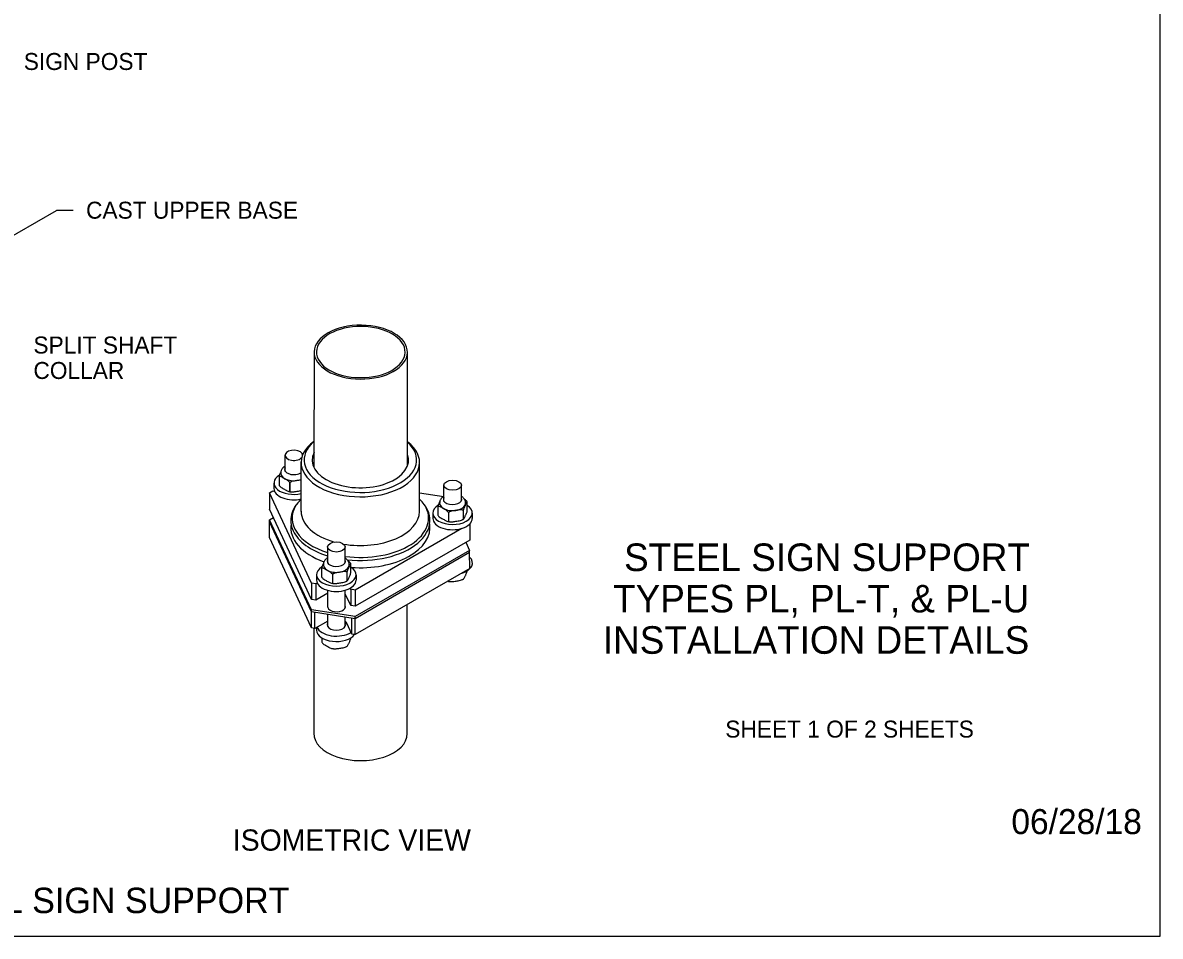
# Model space of a CAD drawing. Extents: x 99862 to 103151, y 100000 to 105076.
# Drawn here: x 102079 to 103151, y 100000 to 100861 of the extents above; entities that cross this region are included whole.
import ezdxf

# ---------------------------------------------------------------- set-up
doc = ezdxf.new("R2010")
doc.units = 0
for name, color, linetype in [('Level 1', 7, 'Continuous'), ('Level 12', 7, 'Continuous'), ('Level 15', 7, 'Continuous'), ('Level 20', 7, 'Continuous'), ('Level 4', 7, 'Continuous'), ('Level 5', 7, 'Continuous'), ('Level 6', 7, 'Continuous'), ('Level 62', 7, 'Continuous'), ('Level 63', 7, 'Continuous'), ('Level 7', 7, 'Continuous')]:
    doc.layers.add(name, color=color, linetype=linetype)

msp = doc.modelspace()

# ---------------------------------------------------------------- linework, layer by layer
at = {"layer": 'Level 1'}
msp.add_lwpolyline([(99862, 99999.5), (103151, 99999.5), (103151, 102075.5), (99862, 102075.5)], close=True, dxfattribs=at)
at = {"layer": 'Level 12'}
for p, q in [((102326.2, 100437.8), (102326.2, 100452.9)), ((102342.8, 100452.9), (102342.8, 100452.9)), ((102320.6, 100433.1), (102320.6, 100424.6)), ((102315.8, 100426.8), (102315.8, 100421.7)), ((102330.7, 100427.2), (102330.7, 100418.8)), ((102330.7, 100418.8), (102330.7, 100427.2)), ((102476, 100409.5), (102476, 100424.7)), ((102492.5, 100409.9), (102492.5, 100424.7)), ((102329.9, 100418.8), (102329.9, 100418.8)), ((102331.8, 100418.5), (102331.8, 100418.5)), ((102470.3, 100404.8), (102470.3, 100396.4)), ((102494.2, 100401.1), (102494.2, 100392.7)), ((102497.9, 100400.7), (102497.9, 100409.1)), ((102465.6, 100398.5), (102465.6, 100393.5)), ((102480.4, 100399), (102480.4, 100390.6)), ((102502.7, 100398.5), (102502.7, 100393.5)), ((102366.4, 100351.3), (102366.4, 100366.5)), ((102382.9, 100351.7), (102382.9, 100366.5)), ((102388.3, 100342.4), (102388.3, 100350.9)), ((102355.9, 100340.3), (102355.9, 100335.3)), ((102360.7, 100346.6), (102360.7, 100338.2)), ((102370.8, 100340.8), (102370.8, 100332.3)), ((102384.6, 100342.9), (102384.6, 100334.5)), ((102393.1, 100340.3), (102393.1, 100335.3)), ((102494.5, 100336.4), (102494.5, 100336.4)), ((102366.4, 100309.9), (102366.4, 100325.6)), ((102382.9, 100309.3), (102382.9, 100325.7)), ((102479.8, 100334.2), (102479.8, 100334.2)), ((102481.7, 100333.9), (102481.7, 100333.9)), ((102493.9, 100336), (102493.8, 100336)), ((102366.4, 100291.5), (102366.4, 100302.9)), ((102382.9, 100291.5), (102382.9, 100300.4)), ((102356, 100290.7), (102356, 100288.1)), ((102360.8, 100280.9), (102360.8, 100276.7)), ((102384.2, 100272.7), (102384.2, 100272.7)), ((102384.8, 100273.1), (102384.8, 100273.1)), ((102370.1, 100270.9), (102370.1, 100270.9)), ((102372.1, 100270.6), (102372.1, 100270.6))]:
    msp.add_line(p, q, dxfattribs=at)
for centre, major_axis, ratio, start_param, end_param in [((102334.5, 100452.9), (-8.26, 0), 0.57735, 3.126776, 9.061237), ((102334.4, 100426.8), (-18.6, 0), 0.57735, 5.527185, 8.246196), ((102334.4, 100436), (-12.2, 0), 0.57735, 0, 2.190456), ((102334.4, 100439.5), (8.72, 0), 0.546299, 2.771788, 5.664646), ((102334.4, 100421.7), (-18.6, 0), 0.57735, 0, 1.962888), ((102484.1, 100411.3), (8.72, 0), 0.546299, 2.771788, 6.566843), ((102484.1, 100398.5), (-18.6, 0), 0.57735, 5.527185, 10.157185), ((102484.1, 100407.8), (-12.2, 0), 0.57735, 0, 3.141593), ((102484.1, 100393.5), (-18.6, 0), 0.57735, 0, 3.141593), ((102374.5, 100340.3), (-18.6, 0), 0.57735, 5.527185, 10.157185), ((102374.5, 100349.6), (-12.2, 0), 0.57735, 0, 3.141593), ((102374.5, 100353), (8.72, 0), 0.546299, 2.771788, 6.566843), ((102484.2, 100351.4), (18.6, 0), 0.57735, 5.200622, 6.819314), ((102374.5, 100335.3), (-18.6, 0), 0.57735, 0, 3.141593), ((102374.6, 100293.2), (-8.77, 0), 0.57735, 5.938484, 9.769479), ((102374.6, 100288.1), (18.6, 0), 0.57735, 3.141593, 5.883676), ((102374.6, 100293.2), (-18.6, 0), 0.57735, 0.209677, 2.408341)]:
    msp.add_ellipse(centre, major_axis=major_axis, ratio=ratio, start_param=start_param, end_param=end_param, dxfattribs=at)
for centre in [(102484.2, 100424.7), (102374.6, 100366.5)]:
    msp.add_ellipse(centre, major_axis=(-8.26, 0), ratio=0.57735, dxfattribs=at)
for points, degree in [([(102322.4, 100437.8), (102321.9, 100436.7), (102321.3, 100435.5), (102320.7, 100433.7), (102320.6, 100433.4), (102320.6, 100433.1)], 3), ([(102330.7, 100427.2), (102330.5, 100427.5), (102330.2, 100427.8), (102328.7, 100429.3), (102327, 100430.2), (102325.6, 100431), (102324.2, 100431.8), (102322.6, 100432.8), (102321, 100433.1), (102320.8, 100433.1), (102320.6, 100433.1)], 3), ([(102326.2, 100442.7), (102325.2, 100442.1), (102324.2, 100441.2), (102323.1, 100439.6), (102322.7, 100438.8), (102322.3, 100437.5), (102322.1, 100436.7), (102322.1, 100436)], 3), ([(102320.6, 100424.6), (102320.8, 100424.3), (102321, 100424.1), (102322.6, 100422.6), (102324.2, 100421.7), (102325.6, 100420.9), (102327, 100420.1), (102328.6, 100419.1), (102329.9, 100418.8)], 3), ([(102341.3, 100429.6), (102340, 100429.5), (102338.7, 100429.3), (102337.6, 100429.1), (102335.7, 100428.8), (102333.4, 100428.6), (102331.3, 100427.6), (102331, 100427.4), (102330.7, 100427.2)], 3), ([(102329.9, 100418.8), (102330.5, 100418.7), (102331.2, 100418.6), (102331.8, 100418.5)], 2), ([(102331.8, 100418.5), (102333.6, 100418.3), (102335.8, 100418.7), (102337.6, 100419), (102338.8, 100419.2), (102340.2, 100419.4), (102341.5, 100419.7)], 3), ([(102476, 100414.5), (102475, 100413.8), (102474, 100412.9), (102472.8, 100411.4), (102472.4, 100410.6), (102472, 100409.3), (102471.9, 100408.5), (102471.9, 100407.8)], 3), ([(102496.4, 100407.8), (102496.4, 100409.1), (102495.9, 100410.6), (102494.6, 100412.7), (102493.5, 100413.6), (102492.5, 100414.3)], 3), ([(102497.9, 100409.1), (102497.7, 100409.4), (102497.5, 100409.7), (102496.7, 100410.5), (102496, 100410.9), (102495.4, 100411.4)], 3), ([(102472.1, 100409.6), (102471.6, 100408.5), (102471, 100407.3), (102470.5, 100405.5), (102470.4, 100405.2), (102470.3, 100404.8)], 3), ([(102480.4, 100399), (102480.2, 100399.3), (102479.9, 100399.6), (102478.4, 100401.1), (102476.8, 100402), (102475.4, 100402.8), (102474, 100403.6), (102472.3, 100404.6), (102470.8, 100404.9), (102470.5, 100404.9), (102470.3, 100404.8)], 3), ([(102494.2, 100401.1), (102493.9, 100401.3), (102493.6, 100401.3), (102491.5, 100401.6), (102489.2, 100401.2), (102487.3, 100400.9), (102485.4, 100400.6), (102483.2, 100400.3), (102481.1, 100399.4), (102480.7, 100399.2), (102480.4, 100399)], 3), ([(102497.9, 100409.1), (102497.9, 100409.1), (102497.8, 100409), (102497.2, 100408.4), (102496.6, 100407.1), (102496.1, 100406), (102495.6, 100404.9), (102495, 100403.6), (102494.4, 100401.8), (102494.3, 100401.5), (102494.2, 100401.1)], 3), ([(102494.3, 100392.8), (102494.4, 100392.8), (102494.5, 100392.8), (102495, 100393.4), (102495.6, 100394.8), (102496.1, 100395.9), (102496.6, 100396.9), (102497.2, 100398.2), (102497.8, 100400), (102497.9, 100400.3), (102497.9, 100400.7)], 3), ([(102470.3, 100396.4), (102470.5, 100396.1), (102470.8, 100395.8), (102472.3, 100394.3), (102474, 100393.5), (102475.4, 100392.7), (102476.7, 100391.9), (102478.3, 100390.9), (102479.6, 100390.6)], 3), ([(102479.6, 100390.6), (102480.3, 100390.5), (102480.9, 100390.4), (102481.6, 100390.3)], 2), ([(102481.6, 100390.3), (102483.3, 100390.1), (102485.5, 100390.5), (102487.3, 100390.8), (102489.2, 100391.1), (102491.5, 100391.4), (102493.4, 100392.2), (102493.6, 100392.3), (102493.7, 100392.4)], 3), ([(102493.7, 100392.4), (102493.9, 100392.5), (102494.1, 100392.6), (102494.3, 100392.7), (102494.3, 100392.7), (102494.3, 100392.8)], 3), ([(102362.5, 100351.3), (102362, 100350.3), (102361.4, 100349.1), (102360.9, 100347.3), (102360.8, 100346.9), (102360.7, 100346.6)], 3), ([(102366.4, 100356.3), (102365.3, 100355.6), (102364.3, 100354.7), (102363.2, 100353.2), (102362.8, 100352.4), (102362.4, 100351), (102362.3, 100350.2), (102362.3, 100349.6)], 3), ([(102386.7, 100349.6), (102386.7, 100350.9), (102386.3, 100352.4), (102384.9, 100354.4), (102383.9, 100355.4), (102382.9, 100356.1)], 3), ([(102388.3, 100350.9), (102388.2, 100350.9), (102388.1, 100350.8), (102387.6, 100350.2), (102387, 100348.8), (102386.5, 100347.7), (102386, 100346.6), (102385.3, 100345.4), (102384.8, 100343.6), (102384.7, 100343.2), (102384.6, 100342.9)], 3), ([(102388.3, 100350.9), (102388.1, 100351.2), (102387.8, 100351.4), (102387, 100352.2), (102386.4, 100352.7), (102385.8, 100353.1)], 3), ([(102370.8, 100340.8), (102370.6, 100341.1), (102370.3, 100341.3), (102368.8, 100342.8), (102367.1, 100343.7), (102365.7, 100344.5), (102364.4, 100345.3), (102362.7, 100346.3), (102361.2, 100346.6), (102360.9, 100346.6), (102360.7, 100346.6)], 3), ([(102360.7, 100338.2), (102360.9, 100337.9), (102361.2, 100337.6), (102362.7, 100336.1), (102364.4, 100335.2), (102365.7, 100334.4), (102367.1, 100333.6), (102368.7, 100332.6), (102370, 100332.4)], 3), ([(102384.6, 100342.9), (102384.3, 100343), (102384, 100343.1), (102381.9, 100343.4), (102379.6, 100343), (102377.7, 100342.7), (102375.8, 100342.4), (102373.6, 100342.1), (102371.5, 100341.2), (102371.1, 100341), (102370.8, 100340.8)], 3), ([(102384.7, 100334.5), (102384.8, 100334.5), (102384.8, 100334.6), (102385.3, 100335.2), (102386, 100336.5), (102386.5, 100337.6), (102387, 100338.7), (102387.6, 100339.9), (102388.1, 100341.8), (102388.2, 100342.1), (102388.3, 100342.4)], 3), ([(102493.8, 100336), (102494, 100336.1), (102494.2, 100336.2), (102494.4, 100336.3), (102494.4, 100336.3), (102494.5, 100336.4)], 3), ([(102494.5, 100336.4), (102494.5, 100336.4), (102494.6, 100336.4), (102495.1, 100337), (102495.7, 100338.4), (102496.2, 100339.5), (102496.7, 100340.6), (102497.3, 100341.8), (102497.9, 100343.6), (102498, 100343.9), (102498, 100344.2)], 3), ([(102370, 100332.4), (102370.7, 100332.3), (102371.3, 100332.2), (102371.9, 100332.1)], 2), ([(102371.9, 100332.1), (102373.7, 100331.9), (102375.9, 100332.3), (102377.7, 100332.6), (102379.6, 100332.9), (102381.9, 100333.1), (102383.8, 100334), (102383.9, 100334.1), (102384.1, 100334.2)], 3), ([(102384.1, 100334.2), (102384.3, 100334.3), (102384.5, 100334.4), (102384.7, 100334.5), (102384.7, 100334.5), (102384.7, 100334.5)], 3), ([(102479.8, 100334.2), (102480.4, 100334.1), (102481.1, 100334), (102481.7, 100333.9)], 2), ([(102481.7, 100333.9), (102483.4, 100333.7), (102485.6, 100334.1), (102487.5, 100334.4), (102489.3, 100334.7), (102491.6, 100335), (102493.5, 100335.8), (102493.7, 100335.9), (102493.9, 100336)], 3), ([(102360.8, 100276.7), (102361, 100276.4), (102361.3, 100276.1), (102362.8, 100274.6), (102364.5, 100273.8), (102365.9, 100273), (102367.2, 100272.2), (102368.9, 100271.2), (102370.1, 100270.9)], 3), ([(102372.1, 100270.6), (102373.8, 100270.4), (102376, 100270.8), (102377.8, 100271.1), (102379.7, 100271.4), (102382, 100271.7), (102383.9, 100272.5), (102384.1, 100272.6), (102384.2, 100272.7)], 3), ([(102384.2, 100272.7), (102384.4, 100272.8), (102384.6, 100272.9), (102384.8, 100273), (102384.8, 100273), (102384.8, 100273.1)], 3), ([(102384.8, 100273.1), (102384.9, 100273.1), (102384.9, 100273.1), (102385.5, 100273.7), (102386.1, 100275.1), (102386.6, 100276.2), (102387.1, 100277.3), (102387.7, 100278.5), (102388.3, 100280.3), (102388.3, 100280.6), (102388.4, 100280.9)], 3), ([(102370.1, 100270.9), (102370.8, 100270.8), (102371.4, 100270.7), (102372.1, 100270.6)], 2)]:
    msp.add_open_spline(points, degree=degree, dxfattribs=at)
at = {"layer": 'Level 15'}
for p in [(102054.4, 100651.3), (102126.7, 100683.8)]:
    msp.add_line(p, (102110.7, 100683.8), dxfattribs=at)
at = {"layer": 'Level 4'}
for p, q in [((102341.5, 100400.1), (102341.5, 100446.9)), ((102453, 100400.1), (102453, 100446.5))]:
    msp.add_line(p, q, dxfattribs=at)
for centre, major_axis, start_param, end_param in [((102397.2, 100446), (-55.8, 0), 5.613202, 10.075608), ((102397.2, 100448.5), (-53, 0), 5.682747, 10.002966), ((102397.2, 100448.5), (-45.4, 0), 6.008223, 9.64062), ((102397.2, 100391.6), (-65.6, 0), 5.728235, 7.364166), ((102397.2, 100391.6), (-65.6, 0), 1.379992, 3.696446), ((102397.2, 100393.8), (-64.3, 0), 5.953629, 7.353253), ((102397.2, 100393.8), (-64.3, 0), 1.345662, 3.471149), ((102397.2, 100400.1), (-55.8, 0), 6.282944, 7.402051), ((102397.2, 100400.1), (-55.8, 0), 1.282094, 3.141666), ((102397.2, 100384.8), (-65.6, 0), 6.192734, 7.303736), ((102397.2, 100384.8), (-65.6, 0), 1.439835, 3.232044)]:
    msp.add_ellipse(centre, major_axis=major_axis, ratio=0.57735, start_param=start_param, end_param=end_param, dxfattribs=at)
at = {"layer": 'Level 5'}
for p, q in [((102353.6, 100550.6), (102353.5, 100441.4)), ((102441.6, 100442.9), (102441.6, 100550.3)), ((102441.4, 100190.4), (102441.3, 100312.1)), ((102353.4, 100289.9), (102353.3, 100190.1))]:
    msp.add_line(p, q, dxfattribs=at)
for centre, major_axis, end_param in [((102397.6, 100550.2), (-44, 0), 12.552004), ((102397.6, 100550.3), (-41.8, 0), 12.552004), ((102397.4, 100190.5), (-44, 0), 9.426883)]:
    msp.add_ellipse(centre, major_axis=major_axis, ratio=0.57735, start_param=6.268969, end_param=end_param, dxfattribs=at)
at = {"layer": 'Level 6'}
for p, q in [((102311.5, 100417.5), (102314.6, 100419.3)), ((102311.5, 100417.5), (102311.5, 100402.2)), ((102351.1, 100332.3), (102311.5, 100417.5)), ((102314.6, 100419.3), (102316.4, 100418.9)), ((102453, 100417.7), (102476, 100414.1)), ((102351.1, 100317), (102311.5, 100402.2)), ((102311.6, 100375.4), (102311.7, 100390.3)), ((102492.8, 100384), (102392.2, 100325.9)), ((102500.3, 100388.2), (102500.3, 100373)), ((102351.2, 100290.2), (102311.6, 100375.4)), ((102500.3, 100373), (102392.2, 100310.6)), ((102500.4, 100346.2), (102500.1, 100361.2)), ((102500.4, 100346.2), (102392.3, 100283.9)), ((102355.2, 100331.7), (102351.1, 100332.3)), ((102351.1, 100332.3), (102351.1, 100317)), ((102356.6, 100332.4), (102355.2, 100331.7)), ((102355.2, 100331.7), (102355.2, 100316.4)), ((102388.1, 100326.6), (102387.6, 100327.6)), ((102392.2, 100325.9), (102388.1, 100326.6)), ((102388.1, 100326.6), (102388.1, 100311.3)), ((102392.2, 100325.9), (102392.2, 100310.6)), ((102355.2, 100316.4), (102351.1, 100317)), ((102366.4, 100322.8), (102355.2, 100316.4)), ((102388.1, 100311.3), (102383.5, 100321.1)), ((102351.2, 100290.2), (102351.2, 100305.3)), ((102354.4, 100289.7), (102354.4, 100304.8)), ((102392.2, 100310.6), (102388.1, 100311.3)), ((102366.4, 100296.7), (102354.4, 100289.7)), ((102389.2, 100284.3), (102384.3, 100294.8)), ((102389.2, 100284.3), (102389.2, 100299.4)), ((102392.3, 100283.9), (102392.3, 100298.9)), ((102354.4, 100289.7), (102351.2, 100290.2)), ((102392.3, 100283.9), (102389.2, 100284.3))]:
    msp.add_line(p, q, dxfattribs=at)
for centre, major_axis, start_param, end_param in [((102374.5, 100320), (-9.22, 0), 3.354509, 3.573425), ((102374.6, 100293.2), (-10.1, 0), 3.423169, 3.757683)]:
    msp.add_ellipse(centre, major_axis=major_axis, ratio=0.57735, start_param=start_param, end_param=end_param, dxfattribs=at)
at = {"layer": 'Level 7'}
for p, q in [((102311.7, 100392.2), (102315.2, 100394.3)), ((102311.7, 100390.3), (102311.7, 100392.2)), ((102351.2, 100307.2), (102311.7, 100392.2)), ((102351.2, 100305.3), (102311.7, 100390.3)), ((102496.5, 100370.9), (102500.1, 100363.1)), ((102500.1, 100363.1), (102392.3, 100300.9)), ((102500.1, 100361.2), (102392.3, 100298.9)), ((102500.1, 100361.2), (102500.1, 100363.1)), ((102351.2, 100305.3), (102351.2, 100307.2)), ((102392.3, 100300.9), (102351.2, 100307.2)), ((102392.3, 100298.9), (102351.2, 100305.3)), ((102392.3, 100298.9), (102392.3, 100300.9))]:
    msp.add_line(p, q, dxfattribs=at)
msp.add_ellipse((102374.7, 100310.3), major_axis=(-8.37, 0), ratio=0.57735, start_param=6.189797, end_param=9.63678, dxfattribs=at)

# ---------------------------------------------------------------- texts
at = {"layer": 'Level 15'}
msp.add_text('06/28/18', height=23.62, dxfattribs=at).set_placement((103010.7, 100095.8))
at = {"layer": 'Level 20'}
for s, p in [('SIGN POST', (102080, 100816.2)), ('SPLIT SHAFT', (102089.1, 100548.9)), ('COLLAR', (102089.1, 100524.9))]:
    msp.add_text(s, height=16, rotation=360, dxfattribs=at).set_placement(p)
for s, height, p in [('CAST UPPER BASE', 16, (102138.7, 100676)), ('ISOMETRIC VIEW', 20, (102277, 100080.2)), ('TYPE PL SIGN SUPPORT', 24, (101947, 100021.3))]:
    msp.add_text(s, height=height, dxfattribs=at).set_placement(p)
at = {"layer": 'Level 62'}
msp.add_text('SHEET 1 OF 2 SHEETS', height=16, dxfattribs=at).set_placement((102741.1, 100186.8))
at = {"layer": 'Level 63'}
for s, p in [('STEEL SIGN SUPPORT', (102645.7, 100343.8)), ('TYPES PL, PL-T, & PL-U', (102635.4, 100304.8)), ('INSTALLATION DETAILS', (102625.7, 100265.8))]:
    msp.add_text(s, height=26, dxfattribs=at).set_placement(p)

doc.saveas('drawing.dxf')
